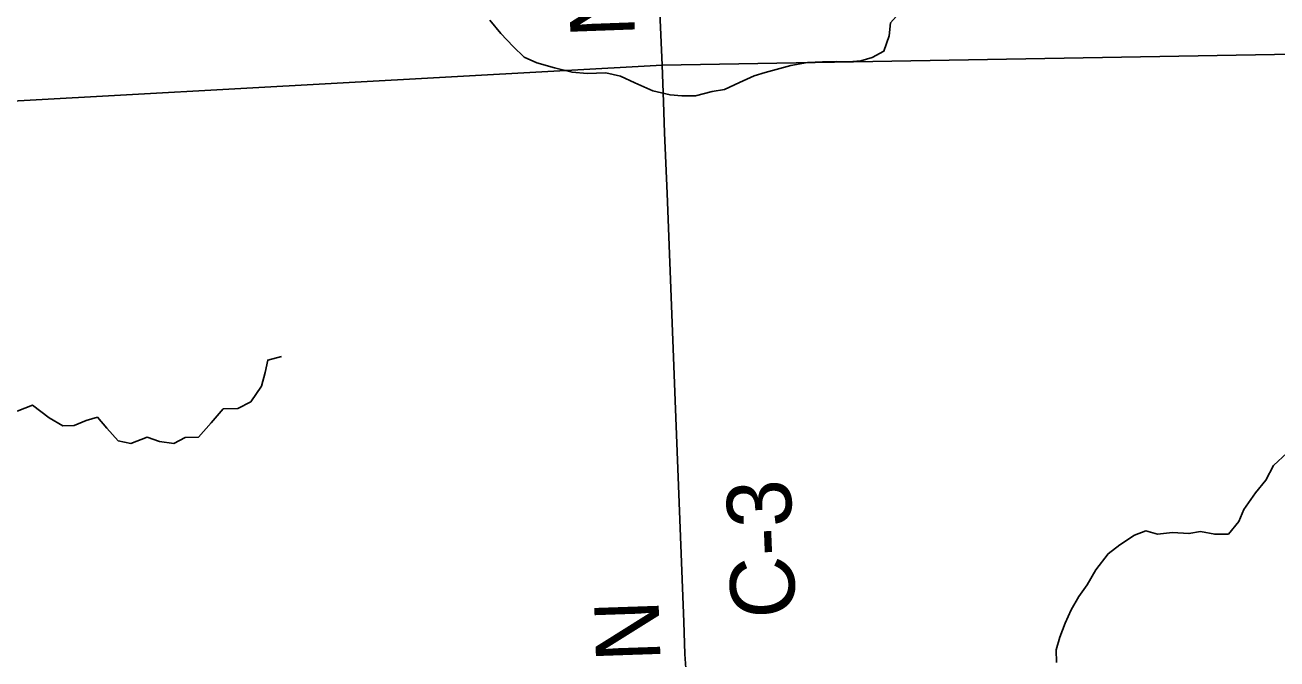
# Model space of a CAD drawing. Extents: x 1442749 to 1756758, y 235267 to 677782.
# Drawn here: x 1583491 to 1589318, y 533523 to 536473 of the extents above; entities that cross this region are included whole.
import ezdxf

# ---------------------------------------------------------------- set-up
doc = ezdxf.new("R2010")
doc.units = 0
for name, color, linetype in [('GM_P_State_Alignment', 7, 'Continuous'), ('GM_X_County_Road', 7, 'Continuous'), ('GM_X_County_Road_Text', 7, 'Continuous'), ('GM_X_Minor_River', 7, 'Continuous')]:
    doc.layers.add(name, color=color, linetype=linetype)

msp = doc.modelspace()

# ---------------------------------------------------------------- linework, layer by layer
at = {"layer": 'GM_P_State_Alignment'}
for points in [[(1586455.9, 536285.6), (1591177.3, 536368.3)], [(1580075.4, 536276.8), (1580481.8, 536026.9), (1580661.3, 535985), (1580870.6, 535967.1), (1581972.2, 536038.6), (1586455.9, 536285.6)]]:
    msp.add_lwpolyline(points, dxfattribs=at)
at = {"layer": 'GM_X_County_Road'}
for points in [[(1586562.5, 533544.8), (1586557.9, 533695.9), (1586533.7, 534289.2), (1586517.8, 534685.9), (1586479.8, 535689.1), (1586467.2, 535971), (1586461.8, 536115.1), (1586455.9, 536285.6), (1586440.9, 536639.4)], [(1586572.3, 533353.1), (1586568.2, 533432.4), (1586565.8, 533480), (1586562.5, 533544.8)]]:
    msp.add_lwpolyline(points, dxfattribs=at)
at = {"layer": 'GM_X_Minor_River'}
for points in [[(1587433.2, 536321.3), (1587487.7, 536350.8), (1587512.6, 536422.7), (1587519.3, 536482.8), (1587574.2, 536544.3), (1587630.6, 536567.8), (1587700.7, 536560.9), (1587820.5, 536529.5), (1587884.8, 536536.8), (1587967.1, 536553.9), (1588055.7, 536586.9), (1588118.5, 536636.4), (1588191, 536671.6), (1588245.5, 536699.1), (1588311.9, 536722.4), (1588376.3, 536745.7), (1588432.7, 536769.2), (1588501.4, 536812.5), (1588564.1, 536863.9), (1588614.6, 536899.4), (1588669, 536922.9), (1588741.4, 536944.1)], [(1585653.5, 536496.2), (1585704.9, 536433.4), (1585762.3, 536372.6), (1585813.8, 536323.8), (1585873.6, 536297.1), (1585955.5, 536274.1), (1586037.4, 536253.1), (1586107.5, 536248.3), (1586193.8, 536251.3), (1586261.7, 536234.5), (1586329.5, 536203.6), (1586413.2, 536166.5), (1586493.2, 536147.6), (1586547.2, 536142.9), (1586611.4, 536144.2), (1586689.8, 536163.4), (1586746, 536172.8), (1586816.6, 536206), (1586885.1, 536237.3), (1586935.4, 536252.8), (1586987.6, 536266.3), (1587056, 536285.5), (1587132.3, 536298.7), (1587202.5, 536301.9), (1587266.7, 536303.2), (1587324.8, 536302.5), (1587380.9, 536305.9), (1587433.2, 536321.3)], [(1583453.2, 534676.2), (1583525.7, 534703.5), (1583603.1, 534644.4), (1583666.9, 534607.6), (1583719, 534609), (1583775.4, 534632.4), (1583827.7, 534647.8), (1583871.2, 534597.2), (1583924.6, 534538.4), (1583982.6, 534525.7), (1584059.1, 534554.9), (1584116.9, 534534.2), (1584183, 534525.4), (1584235.4, 534552.9), (1584297.6, 534554.2), (1584356.5, 534621.7), (1584413.4, 534687.3), (1584481.6, 534688.5), (1584542.1, 534719.9), (1584591, 534791.5), (1584607.8, 534855.5), (1584620.5, 534913.5), (1584684.9, 534930.8)], [(1588291.7, 533505.5), (1588290.4, 533565.7), (1588307.1, 533623.7), (1588332, 533689.6), (1588360.8, 533751.4), (1588395.6, 533813.2), (1588434.3, 533866.9), (1588475.2, 533936.7), (1588532.2, 534012.2), (1588586.8, 534053.7), (1588655.5, 534099.1), (1588707.9, 534118.5), (1588761.8, 534103.9), (1588832, 534111.1), (1588908.1, 534106.2), (1588962.4, 534115.6), (1589028.4, 534102.8), (1589092.5, 534104.1), (1589141.3, 534161.7), (1589164, 534217.6), (1589219, 534295.2), (1589265.9, 534354.8), (1589302.7, 534422.6), (1589365.6, 534482)]]:
    msp.add_lwpolyline(points, dxfattribs=at)

# ---------------------------------------------------------------- texts
at = {"layer": 'GM_X_County_Road_Text'}
for s, rotation, p in [('NELSON', 92.08854, (1586330, 536419.8)), ('C-3', 92.27123, (1587078.8, 533717)), ('N', 91.96013, (1586449, 533513.2))]:
    msp.add_text(s, height=300, rotation=rotation, dxfattribs=at).set_placement(p)

doc.saveas('drawing.dxf')
